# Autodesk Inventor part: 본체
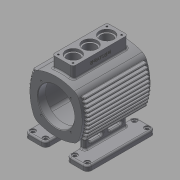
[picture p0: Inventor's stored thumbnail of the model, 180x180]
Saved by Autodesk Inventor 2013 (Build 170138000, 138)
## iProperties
Created: 2015-11
Part Number: 본체
Material: 일반
Document SubType Name: Modeling
Designer: mduedu
Density: 1 g/cm^3
Author: mduedu
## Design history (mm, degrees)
sketch "스케치2"
  geometry: L1 (0, 250)-(0, -250); L2 (250, 0)-(-250, 0); L3 (-50, 50)-(50, 50); L4 (50, 50)-(50, -50); L5 (50, -50)-(-50, -50); L6 (-50, -50)-(-50, 50); A1 r 90 centre (-40, 0) between (40.415, -40.415) and (40.415, 40.415); A2 r 90 centre (40, 0) between (-40.415, 40.415) and (-40.415, -40.415); A3 r 90 centre (0, -40) between (40.415, 40.415) and (-40.415, 40.415); A4 r 90 centre (0, 40) between (-40.415, -40.415) and (40.415, -40.415); 2 further points
  constraints: 12 end point, 8 point on circle, 4 centre point, 4 tangent, 3 perpendicular, 2 horizontal alignment, 2 midpoint, 2 parallel, 2 symmetric about line, 1 coincident, 1 equal radius, 1 horizontal, 1 vertical, 1 vertical alignment, 2 other
  dimensions: "d6" = 500 distance of L1.start L1.end; "d8" = 500 distance of L2.start L2.end; "d9" = 100 distance of L3.end L4.end; "d11" = 90 radius of A3
extrude "돌출1" new body sketch "스케치2" stored distance "d12" = 130; taper "d13" = 0 deg
sketch "스케치3"
  geometry: A1 r 90 centre (40, 0) between (-40.415, 40.415) and (-40.415, -40.415) reference; 2 further points
  constraints: 1 point on circle
fillet "모깎기6" dims "d30" = 15
feature "쉘1" dims "d31" = 15, "d32" = 6, "d33" = 15
sketch "스케치4"
  geometry: L1 (60, -57)-(-60, -57); L2 (-65, 40.415)-(-65, -40.415) reference; L3 (65, -40.415)-(65, 40.415) reference; L4 (-60, -57)-(-60, -45); L5 (60, -57)-(60, -45); L6 (-65, -50)-(65, -50) reference; L7 (-60, -45)-(60, -45); 2 further points
  constraints: 8 end point, 2 parallel, 1 horizontal
  dimensions: "d16" = 5 distance between parallel lines of L7 L6; "d17" = 12 distance of L1.start L5.end; "d23" = 5 distance between parallel lines of L4 L2; "d24" = 5 distance between parallel lines of L5 L3
extrude "돌출2" new body sketch "스케치4" stored distance "d18" = 3; taper "d19" = 0 deg
fillet "모깎기1" dims "d20" = 3
fillet "모깎기4" dims "d25" = 1
sketch "스케치5"
  geometry: C1 r 35 at (0, 0); 1 further point
  constraints: 1 centre point, 1 coincident
  dimensions: "d34" = 70 diameter of C1
extrude "돌출3" cut sketch "스케치5" stored distance "d36" = 3; taper "d37" = 0 deg
feature "결합1"
  node "솔리드2"
fillet "모깎기7" dims "d38" = 1
fillet "모깎기8" dims "d39" = 1
node "작업 평면1"
sketch "스케치6"
  geometry: L1 (-65, -60)-(65, -60); L2 (65, -60)-(65, 60); L3 (65, 60)-(-65, 60); L4 (-65, 60)-(-65, -60); L5 (-65, -60)-(65, 60); L6 (65, -60)-(-65, 60); 1 further point
  constraints: 12 end point, 2 midpoint, 2 parallel, 1 horizontal, 1 perpendicular
  dimensions: "d41" = 120 distance of L3.end L1.start; "d43" = 130 distance of L2.end L3.end
extrude "돌출4" join sketch "스케치6" distance "d44" = 10; taper "d45" = 0 deg
sketch "스케치8"
  geometry: L1 (-60, -70)-(60, -70) reference; L2 (0, -50)-(0, -70); L3 (-30, -44.853)-(-30, -70); L4 (30, -44.853)-(30, -70); L5 (-30, -70)-(30, -70); A1 r 90 centre (0, 40) between (-34.941, -42.941) and (34.941, -42.941) reference; A2 r 90 centre (0, 40) between (-30, -44.853) and (30, -44.853); 1 further point
  constraints: 8 end point, 5 point on circle, 2 perpendicular, 2 symmetric about line, 1 centre point, 1 midpoint, 1 point on line
  dimensions: "d48" = 60 distance between parallel lines of L4 L3
extrude "돌출5" join sketch "스케치8" stored distance "d50" = 80; taper "d51" = 0 deg
sketch "스케치9"
  geometry: L1 (-30, -44.853)-(-30, -70) reference; L2 (30, -70)-(30, -44.853) reference; L3 (-20, -47.75)-(-20, -80); L4 (20, -80)-(20, -47.75); L5 (-48.917, -80)-(48.917, -80) reference; A1 r 90 centre (0, 40) between (-34.941, -42.941) and (34.941, -42.941) reference; 1 further point
  constraints: 4 end point, 2 parallel, 2 point on circle, 2 point on line
  dimensions: "d52" = 10 distance between parallel lines of L2 L4; "d54" = 10 distance between parallel lines of L1 L3 (derived)
extrude "돌출6" cut sketch "스케치9" stored distance "d55" = 80; taper "d56" = 0 deg
fillet "모깎기9" dims "d57" = 8
sketch "스케치10"
  geometry: A1 r 8 centre (-57, 52) between (-57, 60) and (-65, 52) reference; A2 r 8 centre (57, 52) between (65, 52) and (57, 60) reference; A3 r 8 centre (57, 28) between (57, 20) and (65, 28) reference; A4 r 8 centre (-57, 28) between (-65, 28) and (-57, 20) reference; A5 r 8 centre (-57, -28) between (-57, -20) and (-65, -28) reference; A6 r 8 centre (-57, -52) between (-65, -52) and (-57, -60) reference; A7 r 8 centre (57, -52) between (57, -60) and (65, -52) reference; A8 r 8 centre (57, -28) between (65, -28) and (57, -20) reference; 1 further point
hole "구멍1" sketch "스케치10" at (-57, 52), (57, 52), (57, 28), (-57, 28), (-57, -28), (-57, -52), (57, -52), (57, -28) diameter "d58" = 6; stored, may be unused: countersink angle "d62" = 90 deg, drill point angle "d64" = 118 deg; dims "d59" = 6, "d60" = 10, "d61" = 2, "d63" = 8
fillet "모깎기10" dims "d65" = 3
fillet "모깎기11" dims "d66" = 3
fillet "모깎기12" dims "d67" = 3
sketch "스케치11" dims "d72" = 25
  geometry: L1 (65, -50)-(-65, -50) reference; L2 (-80.5, -80)-(80.5, -80) reference; L3 (0, -50)-(0, -80); L4 (-27, -54)-(-10, -54); L5 (-10, -54)-(-10, -62); L6 (-10, -62)-(-27, -62); L7 (-27, -62)-(-27, -54); 3 further points
  constraints: 10 end point, 4 midpoint, 2 parallel, 2 perpendicular, 2 vertical alignment, 1 horizontal, 4 other
  dimensions: "d68" = 8 distance between parallel lines of L6 L4; "d71" = 8 distance from line of point (-27, -58) L1; "d73" = 6 dimension on L3
extrude "돌출7" cut sketch "스케치11" stored distance "d74" = 80; taper "d75" = 0 deg
fillet "모깎기13" dims "d76" = 3
fillet "모깎기14" dims "d78" = 3
sketch "스케치12"
  geometry: L1 (0, 0)-(28.284, 28.284); L2 (0, 0)-(40, 0); A1 r 40 centre (0, 0) between (28.284, 28.284) and (40, 0); 2 further points
  constraints: 4 end point, 2 coincident, 2 point on circle, 1 centre point, 1 horizontal
  dimensions: "d79" = 80 diameter of A1; "d80" = 45 deg angle of L2 L1
hole "구멍2" sketch "스케치12" at (28.284, 28.284) diameter "d82" = 3.242; stored, may be unused: countersink angle "d86" = 90 deg, drill point angle "d88" = 118 deg; dims "d83" = 9, "d84" = 10, "d85" = 2, "d87" = 11
node "작업 평면2"
sketch "스케치13"
  geometry: L1 (-52.5, -20)-(52.5, -20); L2 (52.5, -20)-(52.5, 20); L3 (52.5, 20)-(-52.5, 20); L4 (-52.5, 20)-(-52.5, -20); L5 (-52.5, -20)-(52.5, 20); L6 (52.5, -20)-(-52.5, 20); 1 further point
  constraints: 12 end point, 2 midpoint, 2 parallel, 1 horizontal, 1 perpendicular
  dimensions: "d93" = 105 distance of L2.end L3.end; "d95" = 40 distance of L1.end L2.end
extrude "돌출8" join sketch "스케치13" stored distance "d96" = 80; taper "d97" = 0 deg
fillet "모깎기15" dims "d98" = 5
fillet "모깎기16" dims "d99" = 3
sketch "스케치14"
  geometry: L1 (-52.5, 15)-(-52.5, -15) reference; L2 (52.5, -15)-(52.5, 15) reference; L3 (-52.5, 0)-(52.5, 0); 4 further points
  constraints: 2 end point, 2 midpoint, 2 point on line, 1 coincident
  dimensions: "d100" = 32 distance of point (-32, 0) point (0, 0); "d102" = 32 distance of point (32, 0) point (0, 0) (derived)
hole "구멍3" sketch "스케치14" at (-32, 0), (0, 0), (32, 0) diameter "d103" = 22; stored, may be unused: countersink angle "d107" = 90 deg, drill point angle "d109" = 118 deg; dims "d104" = 8, "d105" = 28, "d106" = 5, "d108" = 10
sketch "스케치15"
  geometry: L1 (46.5, -14)-(-46.5, -14); L2 (-46.5, -14)-(-46.5, 14); L3 (-46.5, 14)-(46.5, 14); L4 (46.5, 14)-(46.5, -14); L5 (46.5, -14)-(-46.5, 14); L6 (-46.5, -14)-(46.5, 14); L7 (47.5, 20)-(-47.5, 20) reference; L8 (-52.5, 15)-(-52.5, -15) reference; 5 further points
  constraints: 12 end point, 4 coincident, 2 midpoint, 2 parallel, 1 horizontal, 1 perpendicular
  dimensions: "d110" = 6 distance between parallel lines of L3 L7; "d111" = 6 distance between parallel lines of L2 L8
hole "구멍4" sketch "스케치15" at (-46.5, 14), (46.5, 14), (46.5, -14), (-46.5, -14) diameter "d112" = 3.242; stored, may be unused: countersink angle "d116" = 90 deg, drill point angle "d118" = 118 deg; dims "d113" = 10, "d114" = 28, "d115" = 5, "d117" = 13
sketch "스케치16"
  geometry: L1 (33.5, 0)-(61.5, 0) reference; L2 (104.5, -150)-(-9.5, -150) reference; L3 (47.5, 0)-(47.5, -150); 2 further points
  constraints: 2 end point, 2 midpoint, 1 point on line, 1 other
  dimensions: "d122" = 11 distance from line of point (47.5, -11) L1
feature "엠보싱2" sketch "스케치16" dims "d16" = 5, "d17" = 12, "d23" = 5, "d24" = 5, "d123" = 0.5, "d124" = 0
chamfer "모따기1" distance "d125" = 1; stored, may be unused: second distance "d126" = 2, angle "d127" = 45 deg
node "솔리드1"
pattern_linear "직사각형 패턴1" dims "d29" = 7
mirror "대칭1"
mirror "대칭2"
pattern_circular "원형 패턴1" dims angle "d90" = 360 deg
mirror "대칭3"
